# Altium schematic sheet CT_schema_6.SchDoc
size 372 x 335 mm
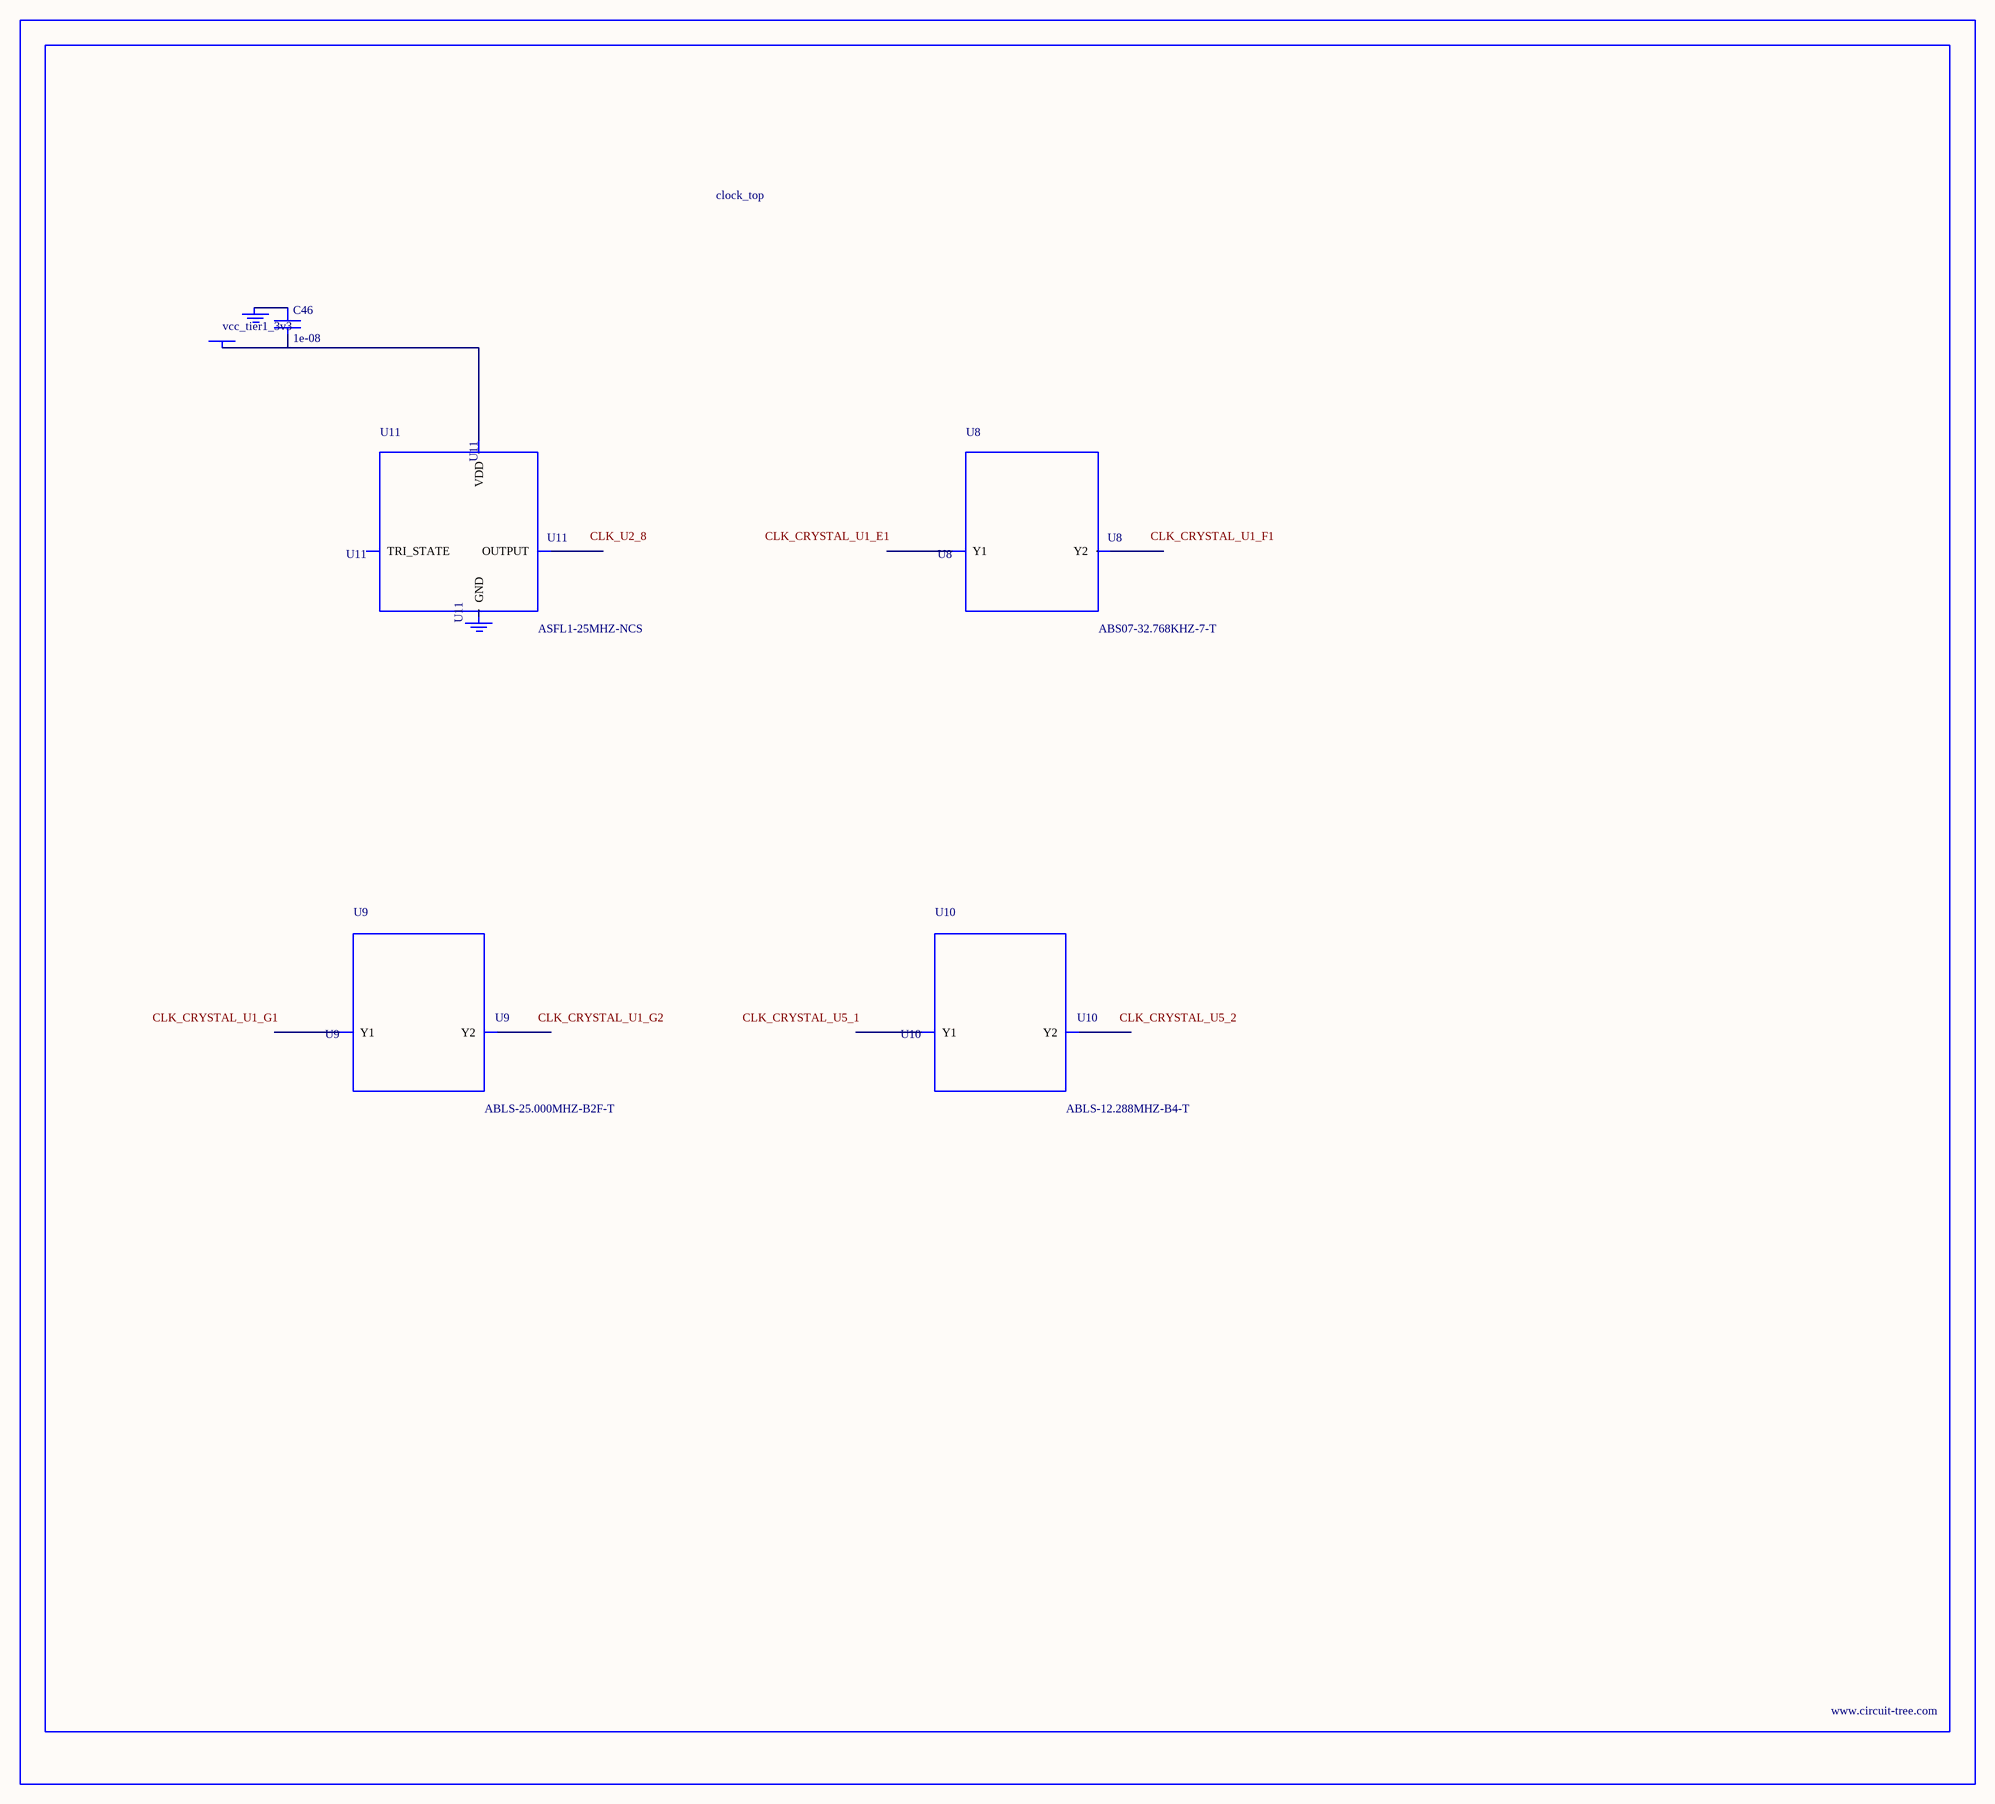
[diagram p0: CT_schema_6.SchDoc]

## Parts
BORDER5  (no value)
C46  1e-08  [C0402]
GND_INSTANCE_5_0  (no value)
GND_INSTANCE_5_1  (no value)
POWER_INSTANCE_5_0  vcc_tier1_3v3
U8  ABS07-32.768KHZ-7-T  [ABS07-32.768KHZ-7-T]
U9  ABLS-25.000MHZ-B2F-T  [ABLS-25.000MHZ-B2F-T]
U10  ABLS-12.288MHZ-B4-T  [ABLS-12.288MHZ-B4-T]
U11  ASFL1-25MHZ-NCS  [ASFL1]

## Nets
NetC46_1: C46.1 GND_INSTANCE_5_0.0(GND)
NetC46_2: C46.2 POWER_INSTANCE_5_0.0(PWR) U11.4(VDD)

Not connected (* = marked no-connect by the designer): GND_INSTANCE_5_1 0(GND); U8 1(Y1) 2(Y2); U9 1(Y1) 2(Y2); U10 1(Y1) 2(Y2); U11 1(TRI_STATE) 2(GND) 3(OUTPUT)

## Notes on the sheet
- Labels drawn without touching a wire or pin: CLK_CRYSTAL_U1_E1, CLK_CRYSTAL_U1_F1, CLK_CRYSTAL_U1_G1, CLK_CRYSTAL_U1_G2, CLK_CRYSTAL_U5_1, CLK_CRYSTAL_U5_2, CLK_U2_8

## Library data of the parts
BORDER5 = BORDER_PAGE5
C46 = C0402C103K3RAC
GND_INSTANCE_5_0 GND_INSTANCE_5_1 = GND
POWER_INSTANCE_5_0 = PWR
